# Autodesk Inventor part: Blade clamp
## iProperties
Created: 2008-06
Part Number: Blade clamp
Document SubType Name: Modeling
Designer: tangg
Density: 7.85 g/cm^3
Mass: 7.32781 g
Surface Area: 54.7426 cm^2
Volume: 7.32781 cm^3
Stock Number: Blade clamp
Material: Steel
Author: tangg
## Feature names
1. Extrusion18
2. Extrusion28
3. Extrusion29
4. Fillet5
5. Extrusion25
6. Extrusion30
7. Mirror2
8. Extrusion31
9. Chamfer1
10. Fillet6
11. Extrusion33
